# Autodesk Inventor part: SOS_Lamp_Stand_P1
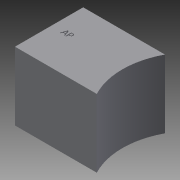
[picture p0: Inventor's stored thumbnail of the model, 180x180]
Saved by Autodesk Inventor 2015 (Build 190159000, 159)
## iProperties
Created: 2016-09
Part Number: SOS_Lamp_Stand_P1
Material: Generisch
Document SubType Name: Modeling
Designer: pichl
Density: 1 g/cm^3
Appearance: Vorgabe
Author: pichl
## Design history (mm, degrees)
sketch "Skizze1"
  geometry: L1 (0, 0)-(0, 40); L2 (0, 40)-(48, 40); L3 (0, 0)-(48, 0); A1 r 42.5 centre (85.5, 20) between (48, 40) and (48, 0); 1 further point
  constraints: 6 end point, 3 point on circle, 1 centre point, 1 horizontal, 1 perpendicular, 1 vertical
  dimensions: "d0" = 40 distance of L1.start L1.end; "d1" = 48 distance of L1.end L2.end; "d2" = 48 distance of L1.start L3.end; "d4" = 42.5 radius of A1
extrude "Extrusion1" new body sketch "Skizze1" distance "d5" = 40; taper "d6" = 0 deg
feature "Wandung1" dims "d7" = 5
sketch "Skizze2"
  geometry: L1 (5, 5)-(35, 5); L2 (35, 5)-(35, 35); L3 (35, 35)-(5, 35); L4 (5, 35)-(5, 5); 1 further point
  constraints: 8 end point, 2 parallel, 1 horizontal, 1 perpendicular
extrude "Extrusion2" join sketch "Skizze2" distance "d11" = 5; taper "d12" = 0 deg
sketch "Skizze3"
  geometry: L1 (6.116, 23.728)-(24.12, 23.728); L2 (24.12, 23.728)-(24.12, 27.536); L3 (24.12, 27.536)-(6.116, 27.536); L4 (6.116, 27.536)-(6.116, 23.728); 1 further point
  constraints: 2 other
extrude "Extrusion3" cut sketch "Skizze3" distance "d13" = 2; taper "d14" = 0 deg
node "Volumenkörper1"
